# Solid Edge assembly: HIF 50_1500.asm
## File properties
Title: Zylinder
Author: bmolnar
Template: iso assembly.asm
Last saved by: bmolnar
Revision: 80
Application: Solid Edge
Username: bmolnar
Dokumentum tartalom típus: 1
Document Number: HIF 50/1500
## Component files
Kit_2.par
Kit_1.par
Profilrohr.par
Kolbenstange.par
Mutter.par
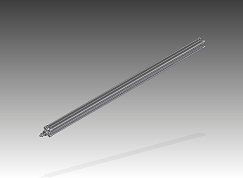
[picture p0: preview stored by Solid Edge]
